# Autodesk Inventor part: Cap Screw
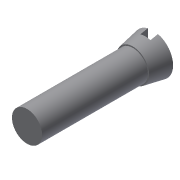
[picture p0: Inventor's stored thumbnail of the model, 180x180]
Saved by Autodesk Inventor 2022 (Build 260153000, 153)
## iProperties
Created: 2002-02
Part Number: Cap Screw
Document SubType Name: Modeling
Designer: ***
Density: 1 g/cm^3
Material: Generic
Appearance: Default
Control State: 0
Master: False
Checked Out: False
Shininess: 77.0
Length Units: 11269
Angle Units: 11279
Time Units: 11290
Mass Units: 11283
Length Display Precision: 3
Angle Display Precision: 2
Density: 0.0
Volumn: 0.0
Area: 0.0
PropertySet Name: Model Information
Author: ***
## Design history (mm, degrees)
sketch "Sketch1"
  geometry: L1 (0, 27.83)-(4, 27.83); L2 (4, 27.83)-(3.25, 23.83); L3 (3.25, 23.83)-(0, 23.83); L4 (0, 23.83)-(0, 27.83)
  constraints: 8 end point, 1 horizontal, 1 parallel, 1 perpendicular, 1 point on line
  dimensions: "d2" = 4 distance from line of L1 L2.end; "d5" = 8 diameter of L1.end L4; "d6" = 6.5 diameter of L3.start L4; "d14" = 4 distance of L3.end L1.start
revolve "Revolution1" sketch "Sketch1" stored, may be unused: angle "d7" = 90 deg
sketch "Sketch2"
  geometry: C1 r 3 at (0, 0)
  constraints: 1 centre point
  dimensions: "d8" = 6 diameter of C1
extrude "Extrusion1" join sketch "Sketch2" distance "d9" = 21; taper "d10" = 0 deg
sketch "Sketch3"
  geometry: L1 (-1, 28.967)-(1, 28.967); L2 (1, 28.967)-(1, 26.33); L3 (1, 26.33)-(-1, 26.33); L4 (-1, 26.33)-(-1, 28.967); L5 (-4, 27.83)-(4, 27.83) reference
  constraints: 8 end point, 2 parallel, 1 horizontal, 1 perpendicular
  dimensions: "d11" = 2 distance of L1.start L1.end; "d15" = 1.5 distance between parallel lines of L5 L3
extrude "Extrusion2" cut sketch "Sketch3" extent not by distance; stored distance "d12" = 24; taper "d13" = 0 deg
body "Solid1"
